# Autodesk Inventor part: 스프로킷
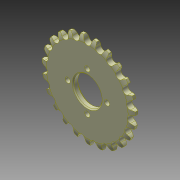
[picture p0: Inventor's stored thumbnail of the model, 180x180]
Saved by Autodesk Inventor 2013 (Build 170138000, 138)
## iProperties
Created: 2024-02
Part Number: 스프로킷
Material: 강철, 합금
Document SubType Name: Modeling
Designer: mdu-01
Density: 1 g/cm^3
Author: mdu-01
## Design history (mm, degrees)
sketch "스케치1"
  geometry: L1 (0, 2.9)-(0, -2.9); L2 (16, 2.9)-(43.6, 2.9); L3 (50, 1.287)-(50, -1.287); L4 (43.6, -2.9)-(16, -2.9); L5 (15, -1.9)-(15, 1.9); L6 (15, 0)-(50, 0); L7 (16, 2.9)-(15, 1.9); L8 (16, -2.9)-(15, -1.9); A1 r 13.5 centre (43.6, -10.6) between (50, 1.287) and (43.6, 2.9); A2 r 13.5 centre (43.6, 10.6) between (43.6, -2.9) and (50, -1.287); 4 further points
  constraints: 16 end point, 6 point on line, 4 point on circle, 3 midpoint, 3 symmetric about line, 2 centre point, 2 parallel, 1 coincident, 1 horizontal, 1 perpendicular, 1 tangent, 1 vertical, 1 other
  dimensions: "d0" = 5.8 distance of L1.start L1.end; "d2" = 100 diameter of L3 L1; "d3" = 30 diameter of L5 L1; "d4" = 6.4 distance from line of A1.centre L3; "d5" = 13.5 radius of A1; "d8" = 1 distance of point (15, 2.9) L5.end; "d9" = 1 distance of L2.start point (15, 2.9); "d10" = 1 distance of L4.end point (15, -2.9)
revolve "회전1" sketch "스케치1" stored, may be unused: angle "d11" = 90 deg
sketch "스케치2"
  geometry: A1 r 46.635 centre (0, 0) between (0, 46.635) and (12.582, 44.906); A2 r 3.885 centre (0, 46.635) between (-3.849, 46.106) and (3.849, 46.106); A3 r 12.7 centre (0, 46.635) between (12.582, 44.906) and (-12.582, 44.906); A4 r 8.815 centre (12.582, 44.906) between (17.817, 51.998) and (3.849, 46.106); A5 r 8.815 centre (-12.582, 44.906) between (-17.817, 51.998) and (-3.849, 46.106); A6 r 30 centre (0, 27.862) between (17.817, 51.998) and (-17.817, 51.998); 1 further point
  constraints: 13 point on circle, 6 centre point, 4 tangent, 2 coincident, 1 vertical alignment
  dimensions: "d12" = 93.27 diameter of A1; "d13" = 7.77 diameter of A2; "d14" = 25.4 diameter of A3; "d15" = 30 radius of A6
extrude "돌출1" cut sketch "스케치2" stored distance "d16" = 10; taper "d17" = 0 deg
sketch "스케치3" dims "d21" = 42
  geometry: 3 further points
  constraints: 2 vertical alignment, 1 coincident, 2 other
hole "구멍1" sketch "스케치3" at (0, -25.635) diameter "d22" = 5.5; stored, may be unused: countersink angle "d26" = 90 deg, drill point angle "d28" = 118 deg; dims "d23" = 6, "d24" = 9.4, "d25" = 2, "d27" = 8
node "솔리드1"
pattern_circular "원형 패턴1" dims angle "d19" = 360 deg
pattern_circular "원형 패턴2" dims angle "d30" = 360 deg
